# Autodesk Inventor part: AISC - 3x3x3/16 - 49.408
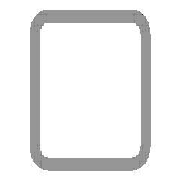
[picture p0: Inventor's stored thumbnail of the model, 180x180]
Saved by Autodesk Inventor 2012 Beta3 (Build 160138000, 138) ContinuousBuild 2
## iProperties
IsCustomPart: 1
Created: 2011-01
Part Number: AISC - 3x3x3/16 - 49.408
Material: Steel, Mild
Description: Tube
Document SubType Name: Modeling
Standard: ANSI
Designer: Beta-8540w
Standards Organization: ANSI
Language: en-US
Size Designation: 3x3x3/16
Categories: <MemberInstance><Categories><Category DisplayName="Structural Shapes" InternalName="089c4875-fa83-4c05-b084-43b9cc11f5ed" Mnemonic="GRDR"><CategoryParameter Dis
Stock Number: 3x3x3/16
Density: 7.86 g/cm^3
G_L: 49.408 in
G_W: 3.000 in
G_H: 3.000 in
+F48483C9-E9F5-4C3B-A2E0-95EBE26CBBEF+CUTDETAIL1: Miter 45.00 deg
_CCFamilyMember: 9
_CCFamilyDisplayName: ANSI AISC (Square) - Tube
_FrameMemberDoc: Frame Member File
_Version: 15.0.0
_GetPNFromCC: 1
Author: Beta-8540w
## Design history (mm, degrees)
node "Start plane"
node "End plane"
sketch "Sketch"
  geometry: L1 (-38.1, -28.575)-(-38.1, 28.575); L2 (-28.575, 38.1)-(28.575, 38.1); L3 (38.1, 28.575)-(38.1, -28.575); L4 (28.575, -38.1)-(-28.575, -38.1); L5 (-28.575, 33.337)-(28.575, 33.338); L6 (33.338, 28.575)-(33.338, -28.575); L7 (28.575, -33.337)-(-28.575, -33.338); L8 (-33.338, -28.575)-(-33.338, 28.575); L9 (0, 56.102)-(0, -56.102) reference; L10 (-56.102, 0)-(56.102, 0) reference; A1 r 9.525 centre (-28.575, -28.575) between (-38.1, -28.575) and (-28.575, -38.1); A2 r 9.525 centre (-28.575, 28.575) between (-28.575, 38.1) and (-38.1, 28.575); A3 r 9.525 centre (28.575, 28.575) between (38.1, 28.575) and (28.575, 38.1); A4 r 9.525 centre (28.575, -28.575) between (28.575, -38.1) and (38.1, -28.575); A5 r 4.763 centre (-28.575, 28.575) between (-28.575, 33.337) and (-33.338, 28.575); A6 r 4.763 centre (28.575, 28.575) between (33.338, 28.575) and (28.575, 33.338); A7 r 4.763 centre (28.575, -28.575) between (28.575, -33.337) and (33.338, -28.575); A8 r 4.763 centre (-28.575, -28.575) between (-33.338, -28.575) and (-28.575, -33.338)
  constraints: 16 end point, 16 point on circle, 8 centre point, 8 tangent, 4 parallel, 3 equal radius, 2 perpendicular, 7 other
  dimensions: "d10" = 76.2 distance between parallel lines of L2 L4 (= G_H); "d11" = 76.2 distance between parallel lines of L1 L3 (= G_W); "d12" = 4.7625 distance between parallel lines of L3 L6 (= G_T); "d15" = 38.1 distance between parallel lines of L2 L10 (= 0.5 x d10); "d16" = 38.1 distance between parallel lines of L9 L3 (= 0.5 x d11); "d17" = 9.525 radius of A1 (= G_IR)
extrude "Body" new body sketch "Sketch" stored distance "d3" = 1254.96513 (= G_L); taper "d4" = 0 deg
node "Driven Length"
  sketch "Sketch3"
    geometry: L1 (0, 0)-(10, 0) reference
    constraints: 2 end point, 1 horizontal
  workplane "Work Plane3"
  sketch "Sketch4"
    geometry: L1 (-2, -35.765)-(12, -35.765) reference; L2 (-2, 1219.2)-(12, 1219.2) reference
    dimensions: "d19" = 1254.96513 distance between parallel lines of L1 L2 (derived)
workplane "Work Plane4"
split "Split1"
body "Solid1"
other parameters: "G_W" = 76.2 [user parameter; used in 1 equation term], "G_H" = 76.2 [user parameter; used in 1 equation term], "G_T" = 4.7625 [user parameter; used in 1 equation term], "G_IR" = 9.525 [user parameter; used in 1 equation term], "G_L" = 1254.96513 (= d19) [user parameter; used in 1 equation term], "G_OFFSET_START" = 35.76513 [user parameter; used in 1 equation term], "G_OFFSET_END" = 0 [user parameter; used in 1 equation term], "d13" = -35.76513 (= -G_OFFSET_START), "d14" = 1219.2 (= G_OFFSET_END + B_L), "B_L" = 1219.2 [user parameter; used in 1 equation term], "d18" = 90 deg
